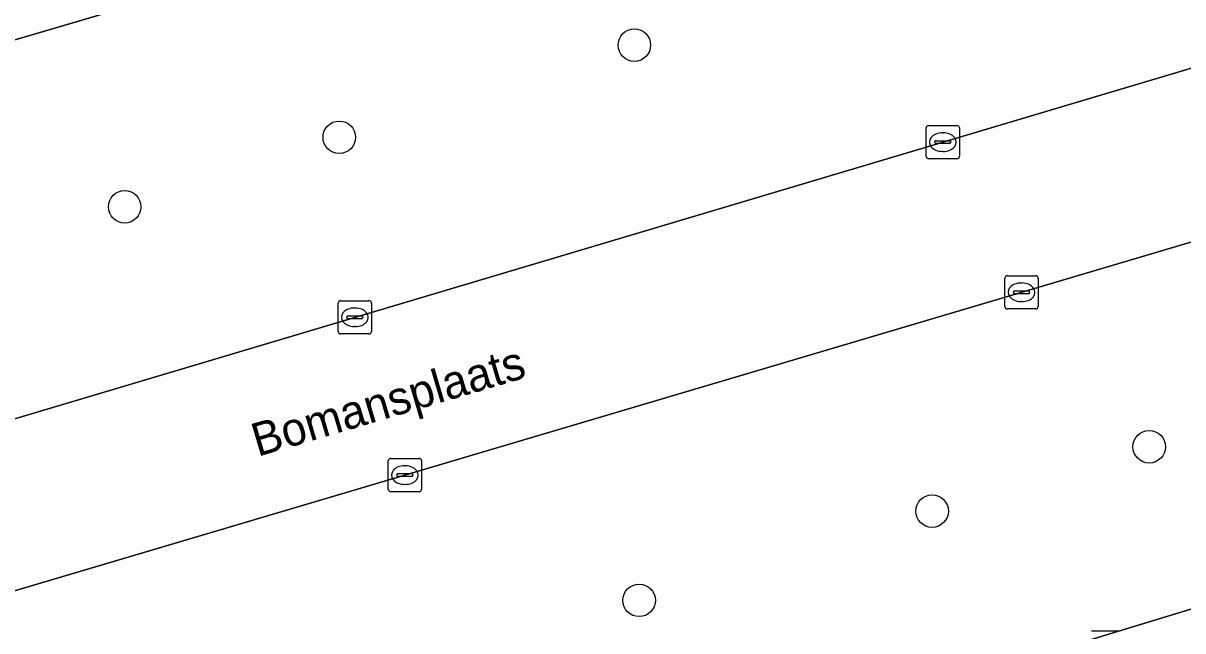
# Model space of a CAD drawing. Extents: x 161347 to 161881, y 382161 to 382804.
# Drawn here: x 161755.37 to 161790.23, y 382379.61 to 382397.88 of the extents above; entities that cross this region are included whole.
import ezdxf

# ---------------------------------------------------------------- set-up
doc = ezdxf.new("R2010")
doc.units = 0
for name, color, linetype in [('IMGEO_Boom', 7, 'Continuous'), ('IMGEO_Kolk', 7, 'Continuous'), ('IMGEO_Openbare_ruimte_label', 7, 'Continuous'), ('IMGEO_Parkeervlak_open', 7, 'Continuous'), ('IMGEO_Rijbaan_lokaal_open', 7, 'Continuous')]:
    doc.layers.add(name, color=color, linetype=linetype)

msp = doc.modelspace()

# ---------------------------------------------------------------- linework, layer by layer
at = {"layer": 'IMGEO_Boom'}
for centre in [(161773.743, 382397.219), (161764.873, 382394.448), (161758.423, 382392.358), (161789.216, 382385.143), (161782.692, 382383.207), (161773.886, 382380.524)]:
    msp.add_circle(centre, 0.489, dxfattribs=at)
at = {"layer": 'IMGEO_Kolk'}
for p, q in [((161782.512, 382393.877), (161782.512, 382394.729)), ((161782.587, 382394.803), (161783.439, 382394.803)), ((161783.513, 382394.729), (161783.513, 382393.877)), ((161783, 382394.583), (161783.025, 382394.583)), ((161782.771, 382394.297), (161782.771, 382394.309)), ((161783.209, 382394.26), (161782.811, 382394.26)), ((161782.814, 382394.346), (161783.212, 382394.346)), ((161783.255, 382394.309), (161783.255, 382394.297)), ((161783.439, 382393.803), (161782.587, 382393.803)), ((161783.023, 382394.023), (161782.998, 382394.023)), ((161784.878, 382389.361), (161784.878, 382390.213)), ((161784.953, 382390.287), (161785.805, 382390.287)), ((161785.879, 382390.213), (161785.879, 382389.361)), ((161785.366, 382390.067), (161785.391, 382390.067)), ((161764.914, 382389.535), (161765.766, 382389.535)), ((161785.137, 382389.781), (161785.137, 382389.793)), ((161785.575, 382389.744), (161785.177, 382389.744)), ((161785.18, 382389.83), (161785.578, 382389.83)), ((161785.389, 382389.507), (161785.364, 382389.507)), ((161785.621, 382389.793), (161785.621, 382389.781)), ((161764.839, 382388.609), (161764.839, 382389.461)), ((161765.327, 382389.315), (161765.352, 382389.315)), ((161765.84, 382389.461), (161765.84, 382388.609)), ((161785.805, 382389.287), (161784.953, 382389.287)), ((161765.098, 382389.029), (161765.098, 382389.041)), ((161765.536, 382388.992), (161765.138, 382388.992)), ((161765.141, 382389.078), (161765.539, 382389.078)), ((161765.582, 382389.041), (161765.582, 382389.029)), ((161765.766, 382388.535), (161764.914, 382388.535)), ((161765.35, 382388.755), (161765.325, 382388.755)), ((161766.345, 382383.866), (161766.345, 382384.718)), ((161766.42, 382384.792), (161767.272, 382384.792)), ((161767.346, 382384.718), (161767.346, 382383.866)), ((161766.604, 382384.286), (161766.604, 382384.298)), ((161766.647, 382384.335), (161767.045, 382384.335)), ((161766.833, 382384.572), (161766.858, 382384.572)), ((161767.088, 382384.298), (161767.088, 382384.286)), ((161767.042, 382384.249), (161766.644, 382384.249)), ((161766.856, 382384.012), (161766.831, 382384.012)), ((161767.272, 382383.792), (161766.42, 382383.792)), ((161787.487, 382379.608), (161788.339, 382379.608))]:
    msp.add_line(p, q, dxfattribs=at)
for points in [[(161782.512, 382393.877), (161782.512, 382394.729)], [(161782.587, 382394.803), (161783.439, 382394.803)], [(161783.513, 382394.729), (161783.513, 382393.877)], [(161783.439, 382393.803), (161782.587, 382393.803)], [(161784.878, 382389.361), (161784.878, 382390.213)], [(161784.953, 382390.287), (161785.805, 382390.287)], [(161785.879, 382390.213), (161785.879, 382389.361)], [(161764.914, 382389.535), (161765.766, 382389.535)], [(161764.839, 382388.609), (161764.839, 382389.461)], [(161765.84, 382389.461), (161765.84, 382388.609)], [(161785.805, 382389.287), (161784.953, 382389.287)], [(161765.766, 382388.535), (161764.914, 382388.535)], [(161766.345, 382383.866), (161766.345, 382384.718)], [(161766.42, 382384.792), (161767.272, 382384.792)], [(161767.346, 382384.718), (161767.346, 382383.866)], [(161767.272, 382383.792), (161766.42, 382383.792)], [(161787.487, 382379.608), (161788.339, 382379.608)]]:
    msp.add_lwpolyline(points, dxfattribs=at)
for centre, radius, start, end in [((161782.589, 382394.727), 0.0765, 91.552, 178.448), ((161782.589, 382394.727), 0.0765, 91.552, 178.448), ((161783.437, 382394.727), 0.0765, 1.552, 88.448), ((161783.437, 382394.727), 0.0765, 1.552, 88.448), ((161782.811, 382394.306), 0.0403, 85.8775, 175.7526), ((161782.808, 382394.296), 0.0366, 178.938, 274.7102), ((161783.212, 382394.303), 0.043, 264.8664, 352.4533), ((161783.216, 382394.308), 0.0386, 1.7309, 96.639), ((161782.589, 382393.879), 0.0765, 181.552, 268.448), ((161782.589, 382393.879), 0.0765, 181.552, 268.448), ((161783.437, 382393.879), 0.0765, 271.552, 358.448), ((161783.437, 382393.879), 0.0765, 271.552, 358.448), ((161784.955, 382390.211), 0.0765, 91.552, 178.448), ((161784.955, 382390.211), 0.0765, 91.552, 178.448), ((161785.803, 382390.211), 0.0765, 1.552, 88.448), ((161785.803, 382390.211), 0.0765, 1.552, 88.448), ((161764.916, 382389.459), 0.0765, 91.552, 178.448), ((161764.916, 382389.459), 0.0765, 91.552, 178.448), ((161765.764, 382389.459), 0.0765, 1.552, 88.448), ((161765.764, 382389.459), 0.0765, 1.552, 88.448), ((161785.177, 382389.79), 0.0403, 85.8775, 175.7526), ((161785.174, 382389.78), 0.0366, 178.938, 274.7102), ((161785.578, 382389.787), 0.043, 264.8664, 352.4533), ((161785.582, 382389.792), 0.0386, 1.7309, 96.639), ((161784.955, 382389.363), 0.0765, 181.552, 268.448), ((161784.955, 382389.363), 0.0765, 181.552, 268.448), ((161785.803, 382389.363), 0.0765, 271.552, 358.448), ((161785.803, 382389.363), 0.0765, 271.552, 358.448), ((161765.138, 382389.038), 0.0403, 85.8775, 175.7526), ((161765.135, 382389.028), 0.0366, 178.938, 274.7102), ((161765.539, 382389.035), 0.043, 264.8664, 352.4533), ((161765.543, 382389.04), 0.0386, 1.7309, 96.639), ((161764.916, 382388.611), 0.0765, 181.552, 268.448), ((161764.916, 382388.611), 0.0765, 181.552, 268.448), ((161765.764, 382388.611), 0.0765, 271.552, 358.448), ((161765.764, 382388.611), 0.0765, 271.552, 358.448), ((161766.422, 382384.716), 0.0765, 91.552, 178.448), ((161766.422, 382384.716), 0.0765, 91.552, 178.448), ((161767.27, 382384.716), 0.0765, 1.552, 88.448), ((161767.27, 382384.716), 0.0765, 1.552, 88.448), ((161766.644, 382384.295), 0.0403, 85.8775, 175.7526), ((161766.641, 382384.285), 0.0366, 178.938, 274.7102), ((161767.045, 382384.292), 0.043, 264.8664, 352.4533), ((161767.049, 382384.297), 0.0386, 1.7309, 96.639), ((161766.422, 382383.868), 0.0765, 181.552, 268.448), ((161766.422, 382383.868), 0.0765, 181.552, 268.448), ((161767.27, 382383.868), 0.0765, 271.552, 358.448), ((161767.27, 382383.868), 0.0765, 271.552, 358.448)]:
    msp.add_arc(centre, radius, start, end, dxfattribs=at)
for centre, major_axis, ratio, start_param, end_param in [((161782.999, 382394.303), (-0.387, 0.002), 0.722429, 4.712389, 7.853982), ((161783.024, 382394.303), (-0.39, 0.002), 0.717154, 1.570796, 4.712389), ((161785.365, 382389.787), (-0.387, 0.002), 0.722429, 4.712389, 7.853982), ((161785.39, 382389.787), (-0.39, 0.002), 0.717154, 1.570796, 4.712389), ((161765.326, 382389.035), (-0.387, 0.002), 0.722429, 4.712389, 7.853982), ((161765.351, 382389.035), (-0.39, 0.002), 0.717154, 1.570796, 4.712389), ((161766.832, 382384.292), (-0.387, 0.002), 0.722429, 4.712389, 7.853982), ((161766.857, 382384.292), (-0.39, 0.002), 0.717154, 1.570796, 4.712389)]:
    msp.add_ellipse(centre, major_axis=major_axis, ratio=ratio, start_param=start_param, end_param=end_param, dxfattribs=at)
at = {"layer": 'IMGEO_Parkeervlak_open'}
for points in [[(161746.473, 382383.289), (161750.131, 382384.5), (161794.688, 382397.782), (161791.477, 382408.079), (161750.141, 382395.914), (161743.218, 382393.745)], [(161799.315, 382382.951), (161796.182, 382392.991), (161750.032, 382379.308), (161747.962, 382378.639), (161749.867, 382372.389), (161751.126, 382368.268)]]:
    msp.add_lwpolyline(points, close=True, dxfattribs=at)
at = {"layer": 'IMGEO_Rijbaan_lokaal_open'}
for points in [[(161750.141, 382395.914), (161791.477, 382408.079), (161794.688, 382397.782), (161750.131, 382384.5), (161746.473, 382383.289), (161743.218, 382393.745)], [(161750.032, 382379.308), (161796.182, 382392.991), (161799.315, 382382.951), (161751.126, 382368.268), (161749.867, 382372.389), (161747.962, 382378.639)]]:
    msp.add_lwpolyline(points, close=True, dxfattribs=at)

# ---------------------------------------------------------------- texts
at = {"layer": 'IMGEO_Openbare_ruimte_label'}
msp.add_text('Bomansplaats', height=1, rotation=16.4962, dxfattribs=at).set_placement((161762.418, 382384.838))

doc.saveas('drawing.dxf')
